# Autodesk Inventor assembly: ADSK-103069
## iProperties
Shininess: 20.0
Created: 2001-03
Part Number: ADSK-103069
Document SubType Name: Assembly
Designer: Administrator
Stock Number: ADSK-103069
Density: 0.0
Volumn: 0.0
Area: 0.0
PropertySet Name: Model Information
Control State: 0
Master: False
Checked Out: False
Author: Administrator
